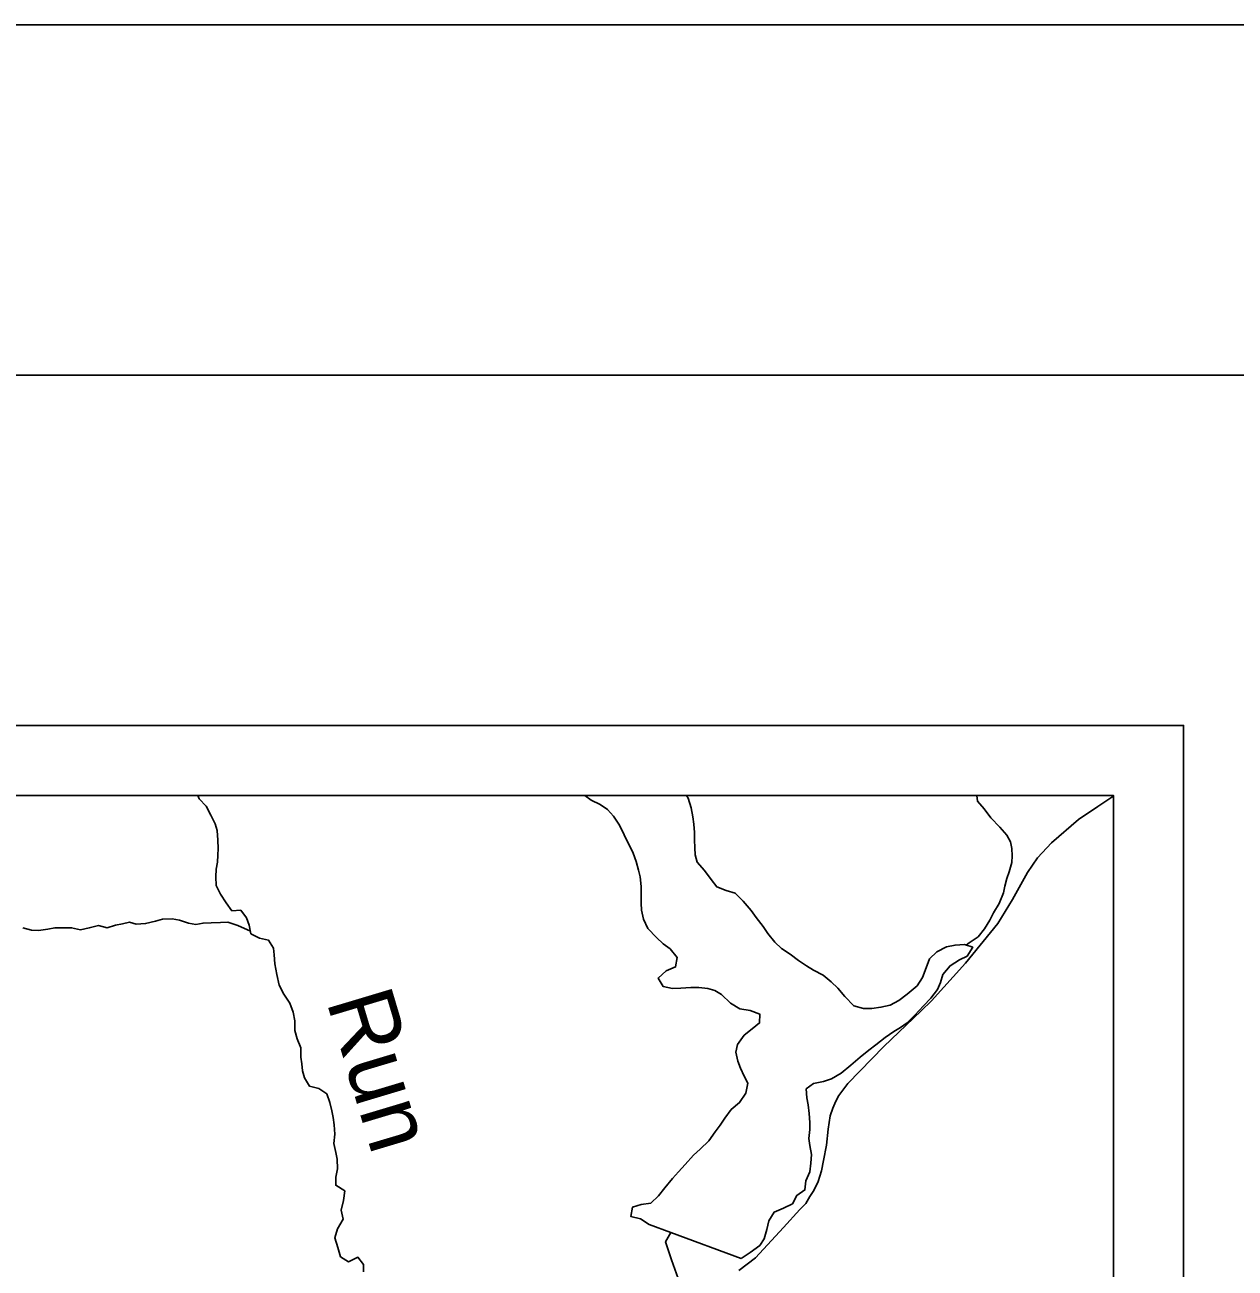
# Model space of a CAD drawing. Extents: x 0 to 34, y 0 to 22.
# Drawn here: x 28.762 to 30.49, y 20.225 to 22 of the extents above; entities that cross this region are included whole.
import ezdxf

# ---------------------------------------------------------------- set-up
doc = ezdxf.new("R2010")
doc.units = 0
for name, color, linetype in [('GM_X_Major_Lake', 7, 'Continuous'), ('GM_X_Major_River', 7, 'Continuous'), ('GM_X_Minor_River', 7, 'Continuous'), ('GM_X_Minor_River_Text', 7, 'Continuous'), ('GM_X_State_Route', 7, 'Continuous'), ('SH_Border', 7, 'Continuous'), ('SH_Cut_Line', 7, 'Continuous'), ('SH_Data', 7, 'Continuous')]:
    doc.layers.add(name, color=color, linetype=linetype)

msp = doc.modelspace()

# ---------------------------------------------------------------- linework, layer by layer
at = {"layer": 'GM_X_Major_Lake'}
for points in [[(29.5619, 20.9), (29.5708, 20.8932), (29.5837, 20.8871), (29.5943, 20.8803), (29.6027, 20.8704), (29.6114, 20.8575), (29.6178, 20.8438), (29.6307, 20.818), (29.6349, 20.8058), (29.6383, 20.7937), (29.6409, 20.7838), (29.6421, 20.7701), (29.6424, 20.7565), (29.6424, 20.7462), (29.6428, 20.7363), (29.6455, 20.7238), (29.6519, 20.7101), (29.664, 20.6976), (29.6735, 20.6885), (29.6834, 20.6812), (29.6936, 20.6687), (29.6913, 20.6554), (29.6777, 20.6497), (29.6663, 20.6395), (29.6735, 20.6277), (29.6868, 20.6247), (29.6989, 20.625), (29.7133, 20.6262), (29.7247, 20.6258), (29.7372, 20.6246), (29.7475, 20.6216), (29.757, 20.6159), (29.7698, 20.6037), (29.7831, 20.5957), (29.7979, 20.5934), (29.8116, 20.5881), (29.8112, 20.5756), (29.8009, 20.5669), (29.7892, 20.5578), (29.7797, 20.5449), (29.7774, 20.5339), (29.78, 20.5209), (29.7838, 20.5111), (29.7891, 20.4993), (29.7945, 20.4894), (29.7918, 20.475), (29.7827, 20.4617), (29.7709, 20.4519)], [(29.7848, 20.2393), (29.7977, 20.2476), (29.8114, 20.2578), (29.8179, 20.2673), (29.8217, 20.2806), (29.8243, 20.2931), (29.8319, 20.3056), (29.8456, 20.3113), (29.8581, 20.3174), (29.8646, 20.3292), (29.8759, 20.3371), (29.8775, 20.35), (29.8828, 20.3629), (29.8843, 20.3754), (29.8855, 20.3876), (29.8828, 20.4005), (29.8817, 20.4104), (29.8828, 20.4233), (29.8832, 20.4335), (29.8821, 20.4464), (29.8806, 20.4586), (29.8787, 20.4685), (29.8779, 20.4814), (29.8882, 20.489), (29.9026, 20.492), (29.914, 20.4958), (29.9276, 20.5037), (29.9417, 20.5151), (29.955, 20.5265), (29.9671, 20.5367), (29.9774, 20.5443), (29.9906, 20.5545), (30.0028, 20.5633), (30.0123, 20.5689), (30.0218, 20.5754), (30.0328, 20.5864), (30.0453, 20.5997), (30.0559, 20.611), (30.0654, 20.6232), (30.0696, 20.6334), (30.073, 20.6448), (30.0833, 20.657), (30.0969, 20.6653), (30.1076, 20.6706), (30.1155, 20.6835), (30.1038, 20.6873), (30.0905, 20.6866), (30.078, 20.6843), (30.0643, 20.6771), (30.0541, 20.6668), (30.0491, 20.6539), (30.0438, 20.6403), (30.0362, 20.6285), (30.0222, 20.6164), (30.01, 20.6073), (29.9975, 20.6008), (29.9846, 20.5978), (29.9717, 20.5959), (29.9596, 20.5959), (29.9459, 20.6001), (29.933, 20.6131), (29.9231, 20.6252), (29.9137, 20.6343), (29.9019, 20.6435), (29.8883, 20.6507), (29.8784, 20.6571), (29.867, 20.6647), (29.8549, 20.6735), (29.8424, 20.6819), (29.8329, 20.6906), (29.823, 20.7031), (29.8162, 20.713), (29.8063, 20.7259), (29.7991, 20.7358), (29.7878, 20.7491), (29.7764, 20.7609), (29.7635, 20.7643), (29.7502, 20.7696), (29.7422, 20.7803), (29.7324, 20.7928), (29.7221, 20.805), (29.7195, 20.8156), (29.7187, 20.8255), (29.7184, 20.8369), (29.7184, 20.8471), (29.7176, 20.8593), (29.7161, 20.8695), (29.7138, 20.8824), (29.7093, 20.8961), (29.707, 20.9)], [(29.7709, 20.4519), (29.7618, 20.4397), (29.755, 20.4295), (29.7477, 20.42), (29.739, 20.4071), (29.7265, 20.3953), (29.717, 20.3866), (29.7048, 20.3733), (29.6957, 20.3631), (29.687, 20.3532), (29.676, 20.3403), (29.6669, 20.3286), (29.6559, 20.318), (29.6422, 20.3161), (29.6297, 20.3123), (29.6274, 20.2994), (29.6411, 20.296), (29.6536, 20.288)], [(29.6536, 20.288), (29.6846, 20.2764)], [(29.6846, 20.2764), (29.7848, 20.2393)]]:
    msp.add_lwpolyline(points, dxfattribs=at)
at = {"layer": 'GM_X_Major_River'}
msp.add_lwpolyline([(29.7205, 20.0283), (29.7109, 20.0522), (29.6859, 20.078), (29.6885, 20.1038), (29.6975, 20.13), (29.6966, 20.1566), (29.6958, 20.1843), (29.695, 20.2105), (29.6854, 20.2374), (29.677, 20.2629), (29.6846, 20.2764)], dxfattribs=at)
at = {"layer": 'GM_X_Minor_River'}
for points in [[(29.1476, 20.5648), (29.1476, 20.5785), (29.1453, 20.591), (29.1407, 20.6039), (29.132, 20.6164), (29.1255, 20.6296), (29.1221, 20.6444), (29.1194, 20.6596), (29.1183, 20.6725), (29.1171, 20.682), (29.1103, 20.6934), (29.0974, 20.6964), (29.0849, 20.7028), (29.0827, 20.715), (29.0789, 20.7256), (29.0705, 20.7366), (29.058, 20.7354), (29.0497, 20.7468), (29.0417, 20.7593), (29.0356, 20.7714), (29.0349, 20.784), (29.0352, 20.795), (29.0371, 20.8048), (29.0379, 20.8147), (29.0382, 20.8242), (29.0378, 20.8363), (29.0367, 20.85), (29.034, 20.8594), (29.028, 20.872), (29.0211, 20.8848), (29.0113, 20.8955), (29.0091, 20.9)], [(30.1063, 20.6865), (30.1104, 20.6897), (30.1232, 20.6984), (30.1323, 20.7098), (30.1402, 20.7223), (30.1451, 20.7326), (30.1531, 20.7458), (30.1595, 20.761), (30.1614, 20.7705), (30.1644, 20.7815), (30.1674, 20.791), (30.1712, 20.8046), (30.1719, 20.8141), (30.1715, 20.8244), (30.1693, 20.8338), (30.1643, 20.8433), (30.1541, 20.8547), (30.1416, 20.8683), (30.1321, 20.8812), (30.1222, 20.8918), (30.1213, 20.9)], [(29.0842, 20.7065), (29.0664, 20.7146), (29.052, 20.7191), (29.0418, 20.7187), (29.0285, 20.7183), (29.0168, 20.718), (29.0062, 20.7161), (28.9959, 20.718), (28.9831, 20.7221), (28.9725, 20.724), (28.9588, 20.7236), (28.949, 20.7206), (28.9346, 20.7172), (28.9213, 20.7164), (28.9119, 20.7194), (28.9017, 20.7171), (28.8918, 20.7152), (28.8797, 20.7111), (28.8672, 20.7145), (28.8543, 20.7111), (28.8415, 20.7084), (28.829, 20.7114), (28.8187, 20.711), (28.8051, 20.711), (28.7949, 20.7091), (28.7816, 20.7076), (28.7718, 20.708), (28.7593, 20.711)], [(29.2456, 20.2201), (29.2456, 20.2308), (29.2377, 20.241), (29.2244, 20.2345), (29.2131, 20.2417), (29.2093, 20.255), (29.2047, 20.2687), (29.2085, 20.2815), (29.2168, 20.2952), (29.2141, 20.3081), (29.2171, 20.3221), (29.219, 20.3358), (29.2061, 20.3437), (29.2061, 20.3555), (29.2088, 20.3673), (29.2084, 20.3809), (29.2065, 20.3904), (29.2034, 20.4033), (29.2049, 20.4165), (29.2041, 20.4298), (29.2026, 20.4404), (29.2007, 20.4499), (29.1977, 20.4621), (29.1935, 20.4742), (29.1821, 20.4821), (29.1689, 20.4852), (29.1613, 20.4973), (29.1586, 20.5072), (29.1575, 20.517), (29.1563, 20.5265), (29.1563, 20.5398), (29.151, 20.553), (29.1476, 20.5648)]]:
    msp.add_lwpolyline(points, dxfattribs=at)
at = {"layer": 'GM_X_State_Route'}
msp.add_lwpolyline([(29.7818, 20.2222), (29.8054, 20.2404), (29.8455, 20.2836), (29.8689, 20.3092), (29.8773, 20.3178), (29.8828, 20.3278), (29.8886, 20.3363), (29.8949, 20.349), (29.8996, 20.3643), (29.9027, 20.3789), (29.907, 20.4012), (29.909, 20.4237), (29.9121, 20.443), (29.9158, 20.4539), (29.9203, 20.4637), (29.9242, 20.4719), (29.9372, 20.4891), (29.9889, 20.5417), (30.0422, 20.5929), (30.0565, 20.6069), (30.1053, 20.661), (30.1512, 20.7173), (30.1725, 20.7517), (30.194, 20.79), (30.208, 20.8112), (30.228, 20.8324), (30.2667, 20.8658), (30.2941, 20.8844), (30.3144, 20.8975), (30.3167, 20.8984)], dxfattribs=at)
at = {"layer": 'SH_Border'}
msp.add_lwpolyline([(1.5, 21.5), (33.5, 21.5), (33.5, 0.5), (1.5, 0.5)], close=True, dxfattribs=at)
at = {"layer": 'SH_Cut_Line'}
msp.add_lwpolyline([(0, 0), (34, 0), (34, 22), (0, 22)], close=True, dxfattribs=at)
at = {"layer": 'SH_Data'}
for points in [[(23.4167, 21), (30.4167, 21), (30.4167, 14), (23.4167, 14)], [(23.5167, 20.9), (30.3167, 20.9), (30.3167, 14.1), (23.5167, 14.1)]]:
    msp.add_lwpolyline(points, close=True, dxfattribs=at)

# ---------------------------------------------------------------- texts
at = {"layer": 'GM_X_Minor_River_Text'}
msp.add_text('Run', height=0.09468, rotation=286.6623, dxfattribs=at).set_placement((29.1924, 20.6068))

doc.saveas('drawing.dxf')
